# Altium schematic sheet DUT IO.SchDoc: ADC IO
size 431 x 279 mm; Date: Not shown in title block; ApprovedBy: Not shown in title block; CheckedBy: Not shown in title block; Author: Not shown in title block; CompanyName: Not shown in title block; Engineer: Not shown in title block; Organization: Not shown in title block; Address1: Not shown in title block; Address2: Not shown in title block; Address3: Not shown in title block; Address4: Not shown in title block; DocumentNumber: 1; Revision: Use project parameter SCH_Rev; SheetNumber: 10; SheetTotal: 15; PageSetup: Record=PageOptions¦CenterHorizontal=True¦CenterVertical=True¦PrintScale=1.00¦XCorrection=1.00¦YCorrection=1.00¦PrintKind=0¦BorderSize=5000000¦LeftOffset=0¦BottomOffset=0¦Orientation=2¦PaperLength=1000¦PaperWidth=1000¦Scale=100¦PaperSource=15¦PrintQuality=600¦MediaType=1¦DitherType=10¦PaperKind=Letter¦PrintScaleMode=1
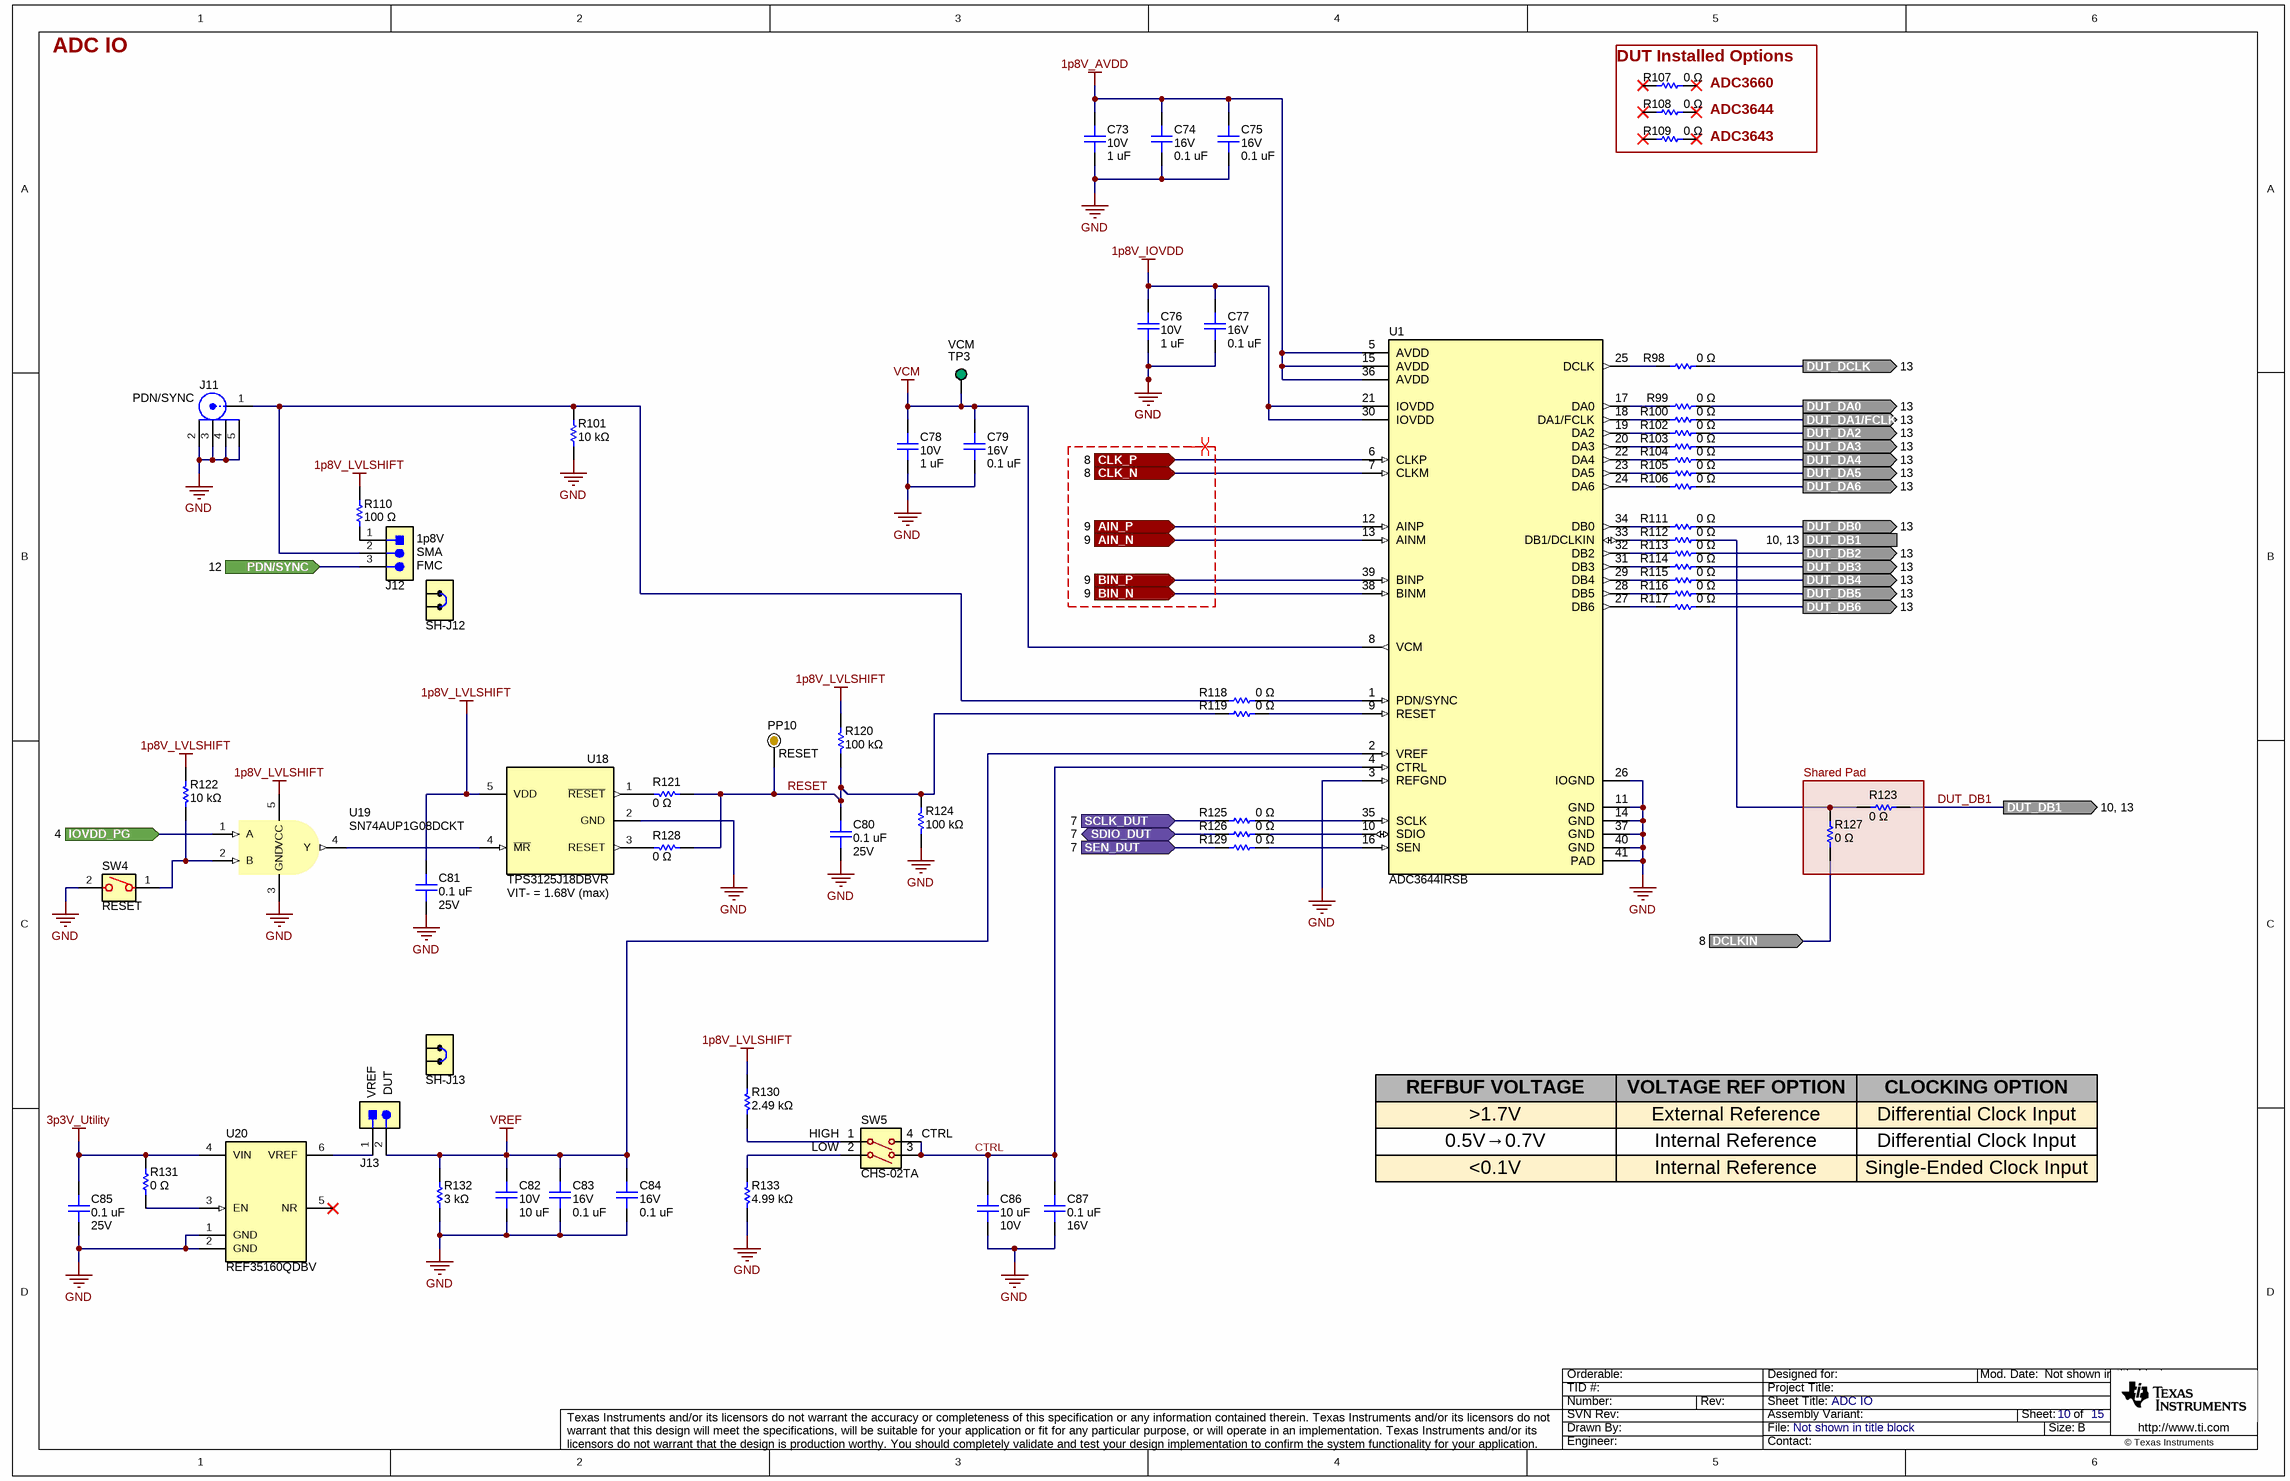
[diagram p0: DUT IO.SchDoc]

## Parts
?  Shared Pad  (graphical)
C73  value 1 uF  Voltage - Rated: 10V  [0201_cap]  (hidden comment: GRM033R61A105ME44D)
C74  value 0.1 uF  Voltage - Rated: 16V  [0201_cap]  (hidden comment: GRM033Z71C104ME14D)
C75  value 0.1 uF  Voltage - Rated: 16V  [0201_cap]  (hidden comment: GRM033Z71C104ME14D)
C76  value 1 uF  Voltage - Rated: 10V  [0201_cap]  (hidden comment: GRM033R61A105ME44D)
C77  value 0.1 uF  Voltage - Rated: 16V  [0201_cap]  (hidden comment: GRM033Z71C104ME14D)
C78  value 1 uF  Voltage - Rated: 10V  [0201_cap]  (hidden comment: GRM033R61A105ME44D)
C79  value 0.1 uF  Voltage - Rated: 16V  [0201_cap]  (hidden comment: GRM033Z71C104ME14D)
C80  value 0.1 uF  Voltage - Rated: 25V  [0402L_cap]  (hidden comment: GRT155R71E104KE01J)
C81  value 0.1 uF  Voltage - Rated: 25V  [0402L_cap]  (hidden comment: GRT155R71E104KE01J)
C82  value 10 uF  Voltage - Rated: 10V  [0402L_cap]  (hidden comment: 0402ZD106MAT2A)
C83  value 0.1 uF  Voltage - Rated: 16V  [0201_cap]  (hidden comment: GRM033Z71C104ME14D)
C84  value 0.1 uF  Voltage - Rated: 16V  [0201_cap]  (hidden comment: GRM033Z71C104ME14D)
C85  value 0.1 uF  Voltage - Rated: 25V  [0402L_cap]  (hidden comment: GRT155R71E104KE01J)
C86  value 10 uF  Voltage - Rated: 10V  [0402L_cap]  (hidden comment: 0402ZD106MAT2A)
C87  value 0.1 uF  Voltage - Rated: 16V  [0201_cap]  (hidden comment: GRM033Z71C104ME14D)
J11  Text1: PDN/SYNC  [FP-132134-15_CONN_SMA_JACK-MFG]  (hidden comment: 132134-15)
J12  Text3: FMC  Text2: SMA  Text1: 1p8V  [PBC03SAAN]  (hidden comment: TSW-103-14-L-S)
J13  Text2: DUT  Text1: VREF  [HDR_2x1_TH_VT_50mil]  (hidden comment: GRPB021VWVN-RC)
PP10  Text1: RESET  [ProbePoint_TH_40mil]  (hidden comment: Probe Point)  (no BOM)
R98  value 0 Ω  [0201]  (hidden comment: ERJ-1GN0R00C)
R99  value 0 Ω  [0201]  (hidden comment: ERJ-1GN0R00C)
R100  value 0 Ω  [0201]  (hidden comment: ERJ-1GN0R00C)
R101  value 10 kΩ  [0402L]  (hidden comment: ERA-2AEB103X)
R102  value 0 Ω  [0201]  (hidden comment: ERJ-1GN0R00C)
R103  value 0 Ω  [0201]  (hidden comment: ERJ-1GN0R00C)
R104  value 0 Ω  [0201]  (hidden comment: ERJ-1GN0R00C)
R105  value 0 Ω  [0201]  (hidden comment: ERJ-1GN0R00C)
R106  value 0 Ω  [0201]  (hidden comment: ERJ-1GN0R00C)
R107  value 0 Ω  [0805L]  (hidden comment: ERJ-6GEY0R00V)
R108  value 0 Ω  [0805L]  (hidden comment: ERJ-6GEY0R00V)
R109  value 0 Ω  [0805L]  (hidden comment: ERJ-6GEY0R00V)
R110  value 100 Ω  [0402L]  (hidden comment: ERJ-2GEJ101X)
R111  value 0 Ω  [0201]  (hidden comment: ERJ-1GN0R00C)
R112  value 0 Ω  [0201]  (hidden comment: ERJ-1GN0R00C)
R113  value 0 Ω  [0201]  (hidden comment: ERJ-1GN0R00C)
R114  value 0 Ω  [0201]  (hidden comment: ERJ-1GN0R00C)
R115  value 0 Ω  [0201]  (hidden comment: ERJ-1GN0R00C)
R116  value 0 Ω  [0201]  (hidden comment: ERJ-1GN0R00C)
R117  value 0 Ω  [0201]  (hidden comment: ERJ-1GN0R00C)
R118  value 0 Ω  [0201]  (hidden comment: ERJ-1GN0R00C)
R119  value 0 Ω  [0201]  (hidden comment: ERJ-1GN0R00C)
R120  value 100 kΩ  [0402L]  (hidden comment: ERJ-2GEJ104X)
R121  value 0 Ω  [0402L]  (hidden comment: ERJ-U020R00X)
R122  value 10 kΩ  [0402L]  (hidden comment: ERA-2AEB103X)
R123  value 0 Ω  [0201]  (hidden comment: ERJ-1GN0R00C)
R124  value 100 kΩ  [0402L]  (hidden comment: ERJ-2GEJ104X)
R125  value 0 Ω  [0201]  (hidden comment: ERJ-1GN0R00C)
R126  value 0 Ω  [0201]  (hidden comment: ERJ-1GN0R00C)
R127  value 0 Ω  [0201]  (hidden comment: ERJ-1GN0R00C)
R128  value 0 Ω  [0402L]  (hidden comment: ERJ-U020R00X)
R129  value 0 Ω  [0201]  (hidden comment: ERJ-1GN0R00C)
R130  value 2.49 kΩ  [0201]  (hidden comment: ERJ-1GNF2491C)
R131  value 0 Ω  [0201]  (hidden comment: ERJ-1GN0R00C)
R132  value 3 kΩ  [0201]  (hidden comment: ERJ-1GNF3001C)
R133  value 4.99 kΩ  [0201]  (hidden comment: ERJ-1GNF4991C)
SH-J12  SPC02SYAN  [SPC02SYAN]  (value not drawn)
SH-J13  HMSC-G  [HMSC-G]  (value not drawn)
SW4  Text1: RESET  [FSMSM]  (hidden comment: FSMSM)
SW5  CHS-02TA  Text4: CTRL  Text2: LOW  Text1: HIGH  [CHS-02TA]
TP3  Text1: VCM  [KEYSTONE5116]  (hidden comment: 5116)
U1  ADC3644IRSB  [RSB0040E]
U18  TPS3125J18DBVR  Text1: VIT- = 1.68V (max)  [DBV0005A]
U19  SN74AUP1G08DCKT  [DCK0005A]
U20  REF35160QDBV  [DBV0006A]

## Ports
AIN_N (in, see 9), AIN_P (in, see 9), BIN_N (in, see 9), BIN_P (in, see 9), CLK_N (in, see 8), CLK_P (in, see 8), DCLKIN (in, see 8), DUT_DA0 (out, see 13), DUT_DA1/FCLK (out, see 13), DUT_DA2 (out, see 13), DUT_DA3 (out, see 13), DUT_DA4 (out, see 13), DUT_DA5 (out, see 13), DUT_DA6 (out, see 13), DUT_DB0 (out, see 13), DUT_DB1 (out, see 10, 13), DUT_DB2 (out, see 13), DUT_DB3 (out, see 13), DUT_DB4 (out, see 13), DUT_DB5 (out, see 13), DUT_DB6 (out, see 13), DUT_DCLK (out, see 13), IOVDD_PG (in, see 4), PDN/SYNC (in, see 12), SCLK_DUT (in, see 7), SDIO_DUT (bidir, see 7), SEN_DUT (in, see 7)

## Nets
1p8V_AVDD: C73.2 C74.2 C75.2 U1.5(AVDD) U1.15(AVDD) U1.36(AVDD)
1p8V_IOVDD: C76.2 C77.2 U1.21(IOVDD) U1.30(IOVDD)
1p8V_LVLSHIFT: C81.2 R110.2 R120.2 R122.1 R130.2 U18.5(VDD) U19.5(VCC)
3p3V_Utility: C85.2 R131.2 U20.4(VIN)
GND: C73.1 C74.1 C75.1 C76.1 C77.1 C78.1 C79.1 C80.1 C81.1 C82.1 C83.1 C84.1 C85.1 C86.1 C87.1 J11.2 J11.3 J11.4 J11.5 R101.1 R124.1 R132.1 R133.1 SW4.2 U1.3(REFGND) U1.11(GND) U1.14(GND) U1.26(IOGND) U1.37(GND) U1.40(GND) U1.41(PAD) U18.2(GND) U19.3(GND) U20.1(GND) U20.2(GND)
VCM: C78.2 C79.2 TP3.1 U1.8(VCM)
VREF: C82.2 C83.2 C84.2 J13.2 R132.2 U1.2(VREF)
AIN_N: U1.13(AINM) ; port AIN_N
AIN_P: U1.12(AINP) ; port AIN_P
BIN_N: U1.38(BINM) ; port BIN_N
BIN_P: U1.39(BINP) ; port BIN_P
CLK_N: U1.7(CLKM) ; port CLK_N
CLK_P: U1.6(CLKP) ; port CLK_P
CTRL: C86.2 C87.2 SW5.3(OFF) SW5.4(OFF) U1.4(CTRL)
DCLKIN: R127.1 ; port DCLKIN
DUT_DA0: R99.2 ; port DUT_DA0
DUT_DA1/FCLK: R100.2 ; port DUT_DA1/FCLK
DUT_DA2: R102.2 ; port DUT_DA2
DUT_DA3: R103.2 ; port DUT_DA3
DUT_DA4: R104.2 ; port DUT_DA4
DUT_DA5: R105.2 ; port DUT_DA5
DUT_DA6: R106.2 ; port DUT_DA6
DUT_DB0: R111.2 ; port DUT_DB0
DUT_DB1: R123.1 ; port DUT_DB1
DUT_DB2: R113.2 ; port DUT_DB2
DUT_DB3: R114.2 ; port DUT_DB3
DUT_DB4: R115.2 ; port DUT_DB4
DUT_DB5: R116.2 ; port DUT_DB5
DUT_DB6: R117.2 ; port DUT_DB6
DUT_DCLK: R98.2 ; port DUT_DCLK
IOVDD_PG: U19.1(A) ; port IOVDD_PG
PDN/SYNC: J12.3 ; port PDN/SYNC
RESET: C80.2 PP10.1 R119.1 R120.1 R121.1 R124.2 R128.1
SCLK_DUT: R125.1 ; port SCLK_DUT
SDIO_DUT: R126.1 ; port SDIO_DUT
SEN_DUT: R129.1 ; port SEN_DUT
NetJ11_1: J11.1 J12.2 R101.2 R118.1
NetJ12_1: J12.1 R110.1
NetJ13_1: J13.1 U20.6(VREF)
NetR98_1: R98.1 U1.25(DCLK)
NetR99_1: R99.1 U1.17(DA0)
NetR100_1: R100.1 U1.18(DA1/FCLK)
NetR102_1: R102.1 U1.19(DA2)
NetR103_1: R103.1 U1.20(DA3)
NetR104_1: R104.1 U1.22(DA4)
NetR105_1: R105.1 U1.23(DA5)
NetR106_1: R106.1 U1.24(DA6)
NetR111_1: R111.1 U1.34(DB0)
NetR112_1: R112.1 U1.33(DB1/DCLKIN)
NetR112_2: R112.2 R123.2 R127.2
NetR113_1: R113.1 U1.32(DB2)
NetR114_1: R114.1 U1.31(DB3)
NetR115_1: R115.1 U1.29(DB4)
NetR116_1: R116.1 U1.28(DB5)
NetR117_1: R117.1 U1.27(DB6)
NetR118_2: R118.2 U1.1(PDN/SYNC)
NetR119_2: R119.2 U1.9(RESET)
NetR121_2: R121.2 U18.1(~{RESET})
NetR122_2: R122.2 SW4.1 U19.2(B)
NetR125_2: R125.2 U1.35(SCLK)
NetR126_2: R126.2 U1.10(SDIO)
NetR128_2: R128.2 U18.3(RESET)
NetR129_2: R129.2 U1.16(SEN)
NetR130_1: R130.1 SW5.1(ON)
NetR131_1: R131.1 U20.3(EN)
NetR133_2: R133.2 SW5.2(ON)
NetU18_4: U18.4(~{MR}) U19.4(Y)

Not connected (* = marked no-connect by the designer): R107 1* 2*; R108 1* 2*; R109 1* 2*; U20 5(NR)*

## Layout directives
differential pair; net class DiffPairIN: (no net found under the mark)

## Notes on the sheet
- ADC3660
- DUT Installed Options
- ADC3644
- ADC3643
- REFBUF VOLTAGE
- VOLTAGE REF OPTION
- CLOCKING OPTION
- >1.7V
- 0.5V→0.7V
- External Reference
- Internal Reference
- Differential Clock Input
- <0.1V
- Single-Ended Clock Input

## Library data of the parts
? = Swizzle: Schematic notation to show that the pads of two components should be overlapped
C73 C76 C78 = capcc09264: CAP CER 1UF 10V X5R 0201; Manufacturer: Murata Electronics; CompType: Capacitor Ceramic; Tolerance: ±20%; SizeX_mm: 0.6; SizeY_mm: 0.3; SizeZ_mm: 0.33
C74 C75 C77 C79 C83 C84 C87 = capcc09270: CAP CER 0.1UF 16V X7R 0201; Manufacturer: Murata Electronics; CompType: Capacitor Ceramic; Tolerance: ±20%; SizeX_mm: 0.6; SizeY_mm: 0.3; SizeZ_mm: 0.33
C80 C81 C85 = capcc09401: CAP CER 0.1UF 25V X7R 0402; Manufacturer: Murata; CompType: Capacitor Ceramic; Tolerance: ±10%; SizeX_mm: 1; SizeY_mm: 0.5; SizeZ_mm: 0.7
C82 C86 = capcc09406: CAP CER 10UF 10V X5R 0402; Manufacturer: KYOCERA AVX; CompType: Capacitor Ceramic; Tolerance: ±20%; SizeX_mm: 1; SizeY_mm: 0.5; SizeZ_mm: 0.7
J11 = 132134-15: SMA Connector Jack, Female Socket 50Ohm Surface Mount, Through Hole Solder; Manufacturer: Amphenol RF; UniqueID: cmp00028; CompType: RF Connector
J12 = TSW-103-14-L-S: Header, 100mil, 3x1, Gold, TH; Manufacturer: Samtec; Alt Manufacturer: Sullins Connector Solutions; UniqueID: cmp00015; Pitch (mm): 2.54
J13 = cmp00298: Header, 50mil, 2x1, Gold, TH; Manufacturer: Sullins Connector Solutions; Pitch (mm): 1.27
PP10 = Probe Point: Probe Point that can be used in lue of a test point; UniqueID: cmp00025
R98-R100 R102-R106 R111-R119 R123 R125-R127 R129 R131 = RSMD020101699: RES SMD 0 OHM JUMPER 1/20W 0201; Manufacturer: Panasonic Electronic Components; CompType: Resistor SMD; Power (Watts): 0.05W, 1/20W
R101 R122 = RSMD040200315: RES SMD 10K OHM 0.1% 1/16W 0402; Manufacturer: Panasonic Electronic Components; CompType: Resistor SMD; Power (Watts): 0.063W, 1/16W; Temperature Coefficient: ±25ppm/°C; SizeX_mm: 1; SizeY_mm: 0.5; SizeZ_mm: 0.4
R107-R109 = RSMD080510615: RES SMD 0 OHM JUMPER 1/8W 0805; Manufacturer: Panasonic Electronic Components; CompType: Resistor SMD; Power (Watts): 0.125W, 1/8W; SizeX_mm: 2; SizeY_mm: 1.25; SizeZ_mm: 0.7
R110 = RSMD040200370: RES SMD 100 OHM 5% 1/10W 0402; Manufacturer: Panasonic Electronic Components; CompType: Resistor SMD; Power (Watts): 0.1W, 1/10W; Temperature Coefficient: ±200ppm/°C; SizeX_mm: 1; SizeY_mm: 0.5; SizeZ_mm: 0.4
R120 R124 = RSMD040200354: RES SMD 100K OHM 5% 1/10W 0402; Manufacturer: Panasonic Electronic Components; CompType: Resistor SMD; Power (Watts): 0.1W, 1/10W; Temperature Coefficient: ±200ppm/°C; SizeX_mm: 1; SizeY_mm: 0.5; SizeZ_mm: 0.4
R121 R128 = RSMD040200004: RES 0 OHM JUMPER 0402 SMD; Manufacturer: Panasonic Electronic Components; CompType: Resistor SMD; Power (Watts): 0.1W, 1/10W; Temperature Coefficient: -100/ +600ppm/°C; SizeX_mm: 1; SizeY_mm: 0.5; SizeZ_mm: 0.4
R130 = RSMD020100692: RES SMD 2.49K OHM 1% 1/20W 0201; Manufacturer: Panasonic Electronic Components; CompType: Resistor SMD; Power (Watts): 0.05W, 1/20W; Temperature Coefficient: ±200ppm/°C
R132 = RSMD020100769: RES SMD 3K OHM 1% 1/20W 0201; Manufacturer: Panasonic Electronic Components; CompType: Resistor SMD; Power (Watts): 0.05W, 1/20W; Temperature Coefficient: ±200ppm/°C
R133 = RSMD020100641: RES SMD 4.99K OHM 1% 1/20W 0201; Manufacturer: Panasonic Electronic Components; CompType: Resistor SMD; Power (Watts): 0.05W, 1/20W; Temperature Coefficient: ±200ppm/°C
SH-J12 = cmp00299: 2 (1 x 2) Position Shunt Connector Black Closed Top 0.050" (1.27mm) Gold; Manufacturer: Adam Tech; PartNumber: HMSC-G; Value: 1x2; Note: You can "mate" this to a header by matching the designator.  i.e. use SH-J3 for header J3; Pitch (mm): 1.27
SH-J13 = HMSC-G: 2 (1 x 2) Position Shunt Connector Black Closed Top 0.050" (1.27mm) Gold; Manufacturer: Adam Tech; Value: 1x2; Key: SPC02SYAN; Note: You can "mate" this to a header by matching the designator.  i.e. use SH-J3 for header J3; Pitch (mm): 1.27
SW4 = cmp00234: SWITCH TACTILE SPST-NO 0.05A 24V; Manufacturer: TE Connectivity; CompType: Push Button
SW5 = CHS-02TA: SWITCH SLIDE DIP SPST 0.1A 6V; Manufacturer: Nidec Components Corporation; CompType: Swtich
TP3 = cmp00057: Test Point, Miniature, Green, TH; Manufacturer: Keystone
U1 = ADC3644IRSB: 14-Bit, 125-MSPS, Low-Noise, Ultra-Low Power Dual Channel ADC, RSB0040B (WQFN-40); Manufacturer: Texas Instruments; Alternate PartNumber: ADC3644IRSBR; PartNumber: ADC3644IRSBT
U18 = cmp00229: Push-pull, supply voltage supervisor with manual reset; Manufacturer: Texas Instruments; Alt PartNumber: TPS3125J18DBVT; CompType: Voltage Detector
U19 = cmp00268: SN74AUP1G08 Low-Power Single 2-Input Positive-AND Gate; Manufacturer: Texas Instruments
U20 = cmp00301: Ultra Low-Power, High-Precision Voltage Reference; Manufacturer: Texas Instruments; Pitch (mm): 1.27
